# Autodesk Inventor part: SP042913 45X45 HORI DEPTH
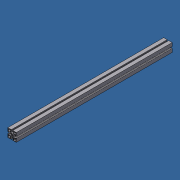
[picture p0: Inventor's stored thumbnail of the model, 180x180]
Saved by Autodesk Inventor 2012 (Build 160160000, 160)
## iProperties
Created: 2013-04
Part Number: SP042913 45X45 HORI DEPTH
Material: Aluminum-6061
Description: PROFILE 45X45 F
Document SubType Name: Modeling
Designer: Admin
Stock Number: 20.1033 PROFILE 45X45 F
Density: 2.71 g/cm^3
FINISH: CLEAR ANODIZED
Author: Admin
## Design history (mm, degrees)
sketch "Sketch1"
  geometry: L1 (-4.1, -22.5)-(-4.1, -18) reference; L2 (-4.6, -18)-(-6.8, -18) reference; L3 (-6.8, -18)-(-6.8, -9.5) reference; L4 (-6.8, -9.5)-(-4.5, -7.2) reference; L5 (-4.5, -7.2)-(4.5, -7.2) reference; L6 (4.5, -7.2)-(6.8, -9.5) reference; L7 (6.8, -9.5)-(6.8, -18) reference; L8 (4.1, -18)-(4.1, -22.5) reference; L9 (22.5, -4.1)-(18, -4.1) reference; L10 (18, -4.6)-(18, -6.8) reference; L11 (18, -6.8)-(9.5, -6.8) reference; L12 (9.5, -6.8)-(7.2, -4.5) reference; L13 (7.2, -4.5)-(7.2, 4.5) reference; L14 (7.2, 4.5)-(9.5, 6.8) reference; L15 (9.5, 6.8)-(18, 6.8) reference; L16 (18, 4.1)-(22.5, 4.1) reference; L17 (22.5, 22.5)-(22.5, 4.4) reference; L18 (4.1, 22.5)-(4.1, 18) reference; L19 (4.6, 18)-(6.8, 18) reference; L20 (6.8, 18)-(6.8, 9.5) reference; L21 (6.8, 9.5)-(4.5, 7.2) reference; L22 (4.5, 7.2)-(-4.5, 7.2) reference; L23 (-4.5, 7.2)-(-6.8, 9.5) reference; L24 (-6.8, 9.5)-(-6.8, 18) reference; L25 (-4.1, 18)-(-4.1, 22.5) reference; L26 (-22.5, 22.5)-(-4.4, 22.5) reference; L27 (-22.5, 4.1)-(-18, 4.1) reference; L28 (-18, 6.8)-(-9.5, 6.8) reference; L29 (-9.5, 6.8)-(-7.2, 4.5) reference; L30 (-7.2, 4.5)-(-7.2, -4.5) reference; L31 (-7.2, -4.5)-(-9.5, -6.8) reference; L32 (-9.5, -6.8)-(-18, -6.8) reference; L33 (-18, -6.8)-(-18, -4.6) reference; L34 (-18, -4.1)-(-22.5, -4.1) reference; L35 (-22.5, -22.5)-(-22.5, -4.4) reference; L36 (-4.4, -22.5)-(-22.5, -22.5) reference; L37 (-4.596, -3.182)-(-3.263, -1.849) reference; L38 (-3.263, 1.849)-(-4.596, 3.182) reference; L39 (-4.596, 3.182)-(-3.182, 4.596) reference; L40 (-3.182, 4.596)-(-1.849, 3.263) reference; L41 (1.849, 3.263)-(3.182, 4.596) reference; L42 (3.182, 4.596)-(4.596, 3.182) reference; L43 (4.596, 3.182)-(3.263, 1.849) reference; L44 (3.263, -1.849)-(4.596, -3.182) reference; L45 (4.596, -3.182)-(3.182, -4.596) reference; L46 (3.182, -4.596)-(1.849, -3.263) reference; L47 (-1.849, -3.263)-(-3.182, -4.596) reference; L48 (-3.182, -4.596)-(-4.596, -3.182) reference; L49 (13.8, -8.8)-(20.5, -8.8) reference; L50 (20.5, -8.8)-(20.5, -15.5) reference; L51 (15.5, -20.5)-(8.8, -20.5) reference; L52 (8.8, -20.5)-(8.8, -13.8) reference; L53 (8.8, 13.8)-(8.8, 20.5) reference; L54 (8.8, 20.5)-(15.5, 20.5) reference; L55 (20.5, 15.5)-(20.5, 8.8) reference; L56 (20.5, 8.8)-(13.8, 8.8) reference; L57 (-13.8, 8.8)-(-20.5, 8.8) reference; L58 (-20.5, 8.8)-(-20.5, 15.5) reference; L59 (-15.5, 20.5)-(-8.8, 20.5) reference; L60 (-8.8, 20.5)-(-8.8, 13.8) reference; L61 (-8.8, -13.8)-(-8.8, -20.5) reference; L62 (-8.8, -20.5)-(-15.5, -20.5) reference; L63 (-20.5, -15.5)-(-20.5, -8.8) reference; L64 (-20.5, -8.8)-(-13.8, -8.8) reference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; A1 r 3.75 centre (0, 0) between (3.362, -1.66) and (3.362, 1.66) reference; A2 r 5 centre (13.8, -13.8) between (13.8, -8.8) and (8.8, -13.8) reference; A3 r 5 centre (15.5, -15.5) between (15.5, -20.5) and (20.5, -15.5) reference; A4 r 5 centre (13.8, 13.8) between (8.8, 13.8) and (13.8, 8.8) reference; A5 r 5 centre (15.5, 15.5) between (20.5, 15.5) and (15.5, 20.5) reference; A6 r 5 centre (-13.8, 13.8) between (-13.8, 8.8) and (-8.8, 13.8) reference; A7 r 5 centre (-15.5, 15.5) between (-15.5, 20.5) and (-20.5, 15.5) reference; A8 r 5 centre (-13.8, -13.8) between (-8.8, -13.8) and (-13.8, -8.8) reference; A9 r 5 centre (-15.5, -15.5) between (-20.5, -15.5) and (-15.5, -20.5) reference; A10 r 3.75 centre (0, 0) between (3.362, 1.66) and (3.263, 1.849) reference; A11 r 3.75 centre (0, 0) between (1.849, 3.263) and (-1.66, 3.362) reference; A12 r 3.75 centre (0, 0) between (-1.66, 3.362) and (-1.849, 3.263) reference; A13 r 3.75 centre (0, 0) between (-3.263, 1.849) and (-3.263, -1.849) reference; A14 r 3.75 centre (0, 0) between (-1.849, -3.263) and (-1.66, -3.362) reference; A15 r 3.75 centre (0, 0) between (-1.66, -3.362) and (1.849, -3.263) reference; A16 r 3.75 centre (0, 0) between (3.263, -1.849) and (3.362, -1.66) reference
  constraints: 160 end point, 32 point on circle, 30 horizontal, 30 vertical, 16 centre point, 144 other
extrude "Extrusion1" new body sketch "Sketch1" stored distance "d0" = 773.6 (computed from DEPTH, TOP_OVERHANG); taper "d1" = 0 deg
body "Solid1"
other parameters: "TOP_OVERHANG" = 25.4 [user parameter; used in 1 equation term], "LEVELER_HEIGHT" = 44.45 [user parameter], "TABLE_TOP_THICKNESS" = 12.7 [user parameter], "DEPTH" = 914.4 [user parameter; used in 1 equation term], "Height" = 1066.8 [user parameter], "LOWER_INSET" = 203.2 [user parameter], "Width" = 1828.8 [user parameter]
